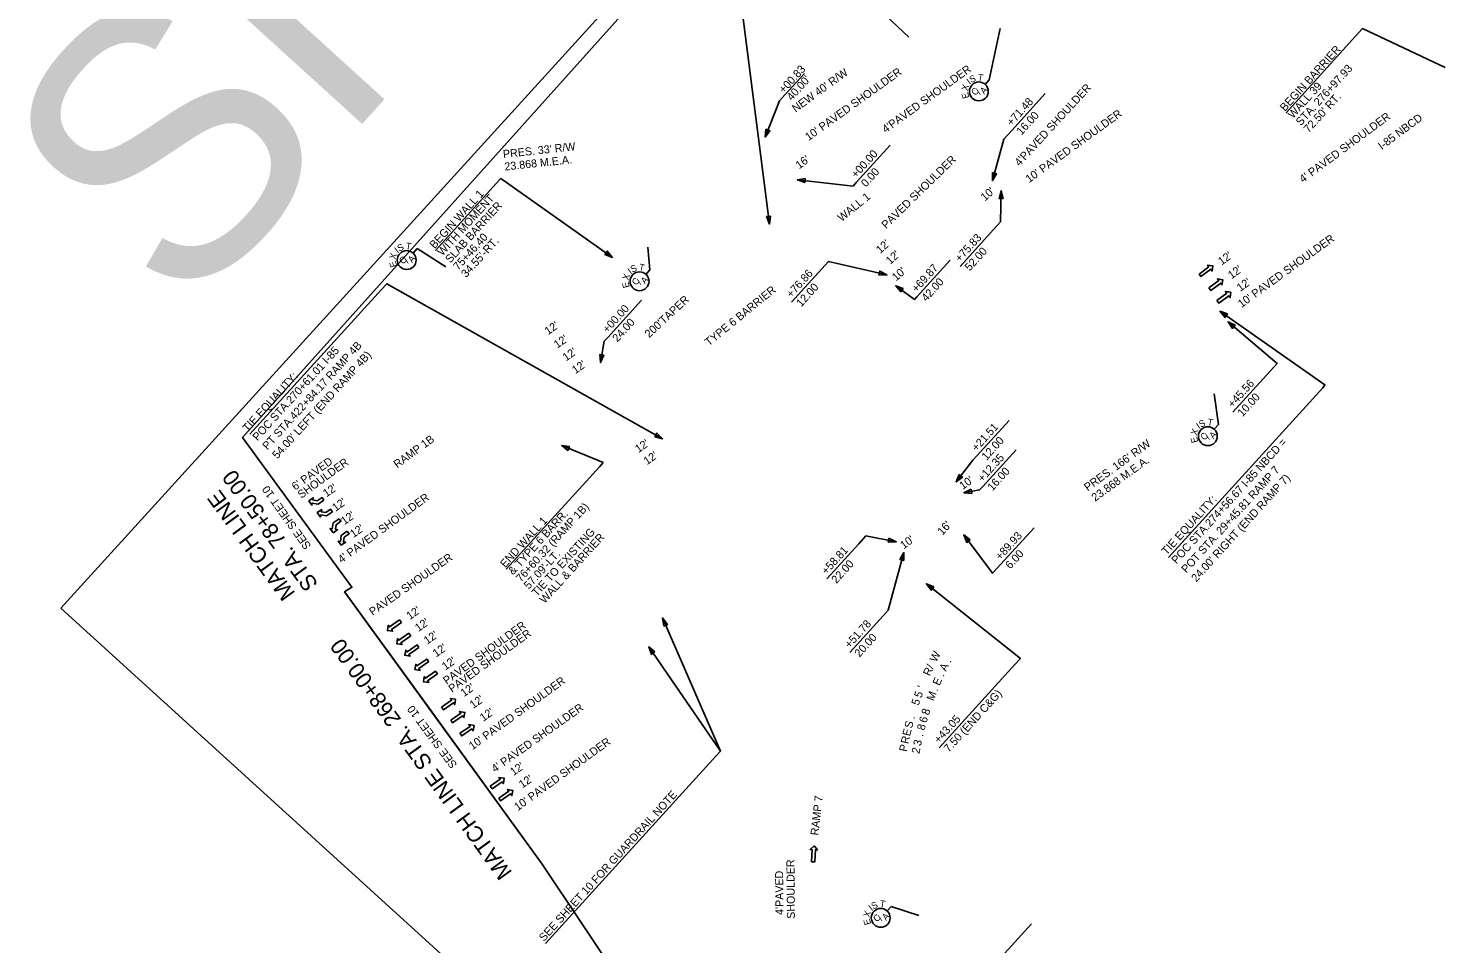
# Model space of a CAD drawing. Extents: x 1608705 to 1610581, y 1091647 to 1093887.
# Drawn here: x 1608705 to 1609761, y 1092394 to 1093080 of the extents above; entities that cross this region are included whole.
import ezdxf

# ---------------------------------------------------------------- set-up
doc = ezdxf.new("R2010")
doc.units = 0
for name, color, linetype in [('Level 14', 7, 'Continuous'), ('Level 2', 7, 'Continuous'), ('Plan_Clip', 7, 'Continuous'), ('RD_EX_Control_Access', 7, 'Continuous'), ('RD_EX_RW_TX', 7, 'Continuous'), ('RD_PD_GR_TX', 7, 'Continuous'), ('RD_PD_RW_TX', 7, 'Continuous'), ('RD_SHT_MatchLine', 7, 'Continuous'), ('RD_SHT_Misc1', 7, 'Continuous'), ('RD_SHT_TX', 7, 'Continuous'), ('RD_TX_RoadID', 7, 'Continuous'), ('RD_TX_RW', 7, 'Continuous')]:
    doc.layers.add(name, color=color, linetype=linetype)

msp = doc.modelspace()

# ---------------------------------------------------------------- linework, layer by layer
at = {"layer": 'Level 14'}
for points in [[(1609582.6, 1092896), (1609584, 1092894.1), (1609591.4, 1092899.6), (1609592.3, 1092898.3), (1609592.9, 1092902.2), (1609589, 1092902.8), (1609589.9, 1092901.5)], [(1609590, 1092885.6), (1609591.4, 1092883.7), (1609598.8, 1092889.2), (1609599.7, 1092887.9), (1609600.3, 1092891.8), (1609596.4, 1092892.4), (1609597.3, 1092891.1)], [(1609596, 1092876.2), (1609597.4, 1092874.3), (1609604.8, 1092879.7), (1609605.8, 1092878.4), (1609606.4, 1092882.4), (1609602.4, 1092883), (1609603.4, 1092881.7)], [(1608926.5, 1092726.4), (1608922.1, 1092723.4), (1608917.7, 1092724.2), (1608917.4, 1092722.6), (1608915.1, 1092725.9), (1608918.4, 1092728.2), (1608918.1, 1092726.6), (1608921.5, 1092725.9), (1608925.1, 1092728.4)], [(1608932.9, 1092717.6), (1608928.5, 1092714.6), (1608924.1, 1092715.4), (1608923.8, 1092713.8), (1608921.5, 1092717.1), (1608924.8, 1092719.4), (1608924.5, 1092717.8), (1608927.9, 1092717.1), (1608931.5, 1092719.6)], [(1608937.8, 1092712.5), (1608939.2, 1092710.6), (1608935.6, 1092708), (1608935.1, 1092704.6), (1608936.7, 1092704.3), (1608933.4, 1092702), (1608931.1, 1092705.3), (1608932.7, 1092705), (1608933.5, 1092709.4)], [(1608943.9, 1092703.1), (1608945.3, 1092701.1), (1608941.7, 1092698.6), (1608941.1, 1092695.1), (1608942.7, 1092694.9), (1608939.5, 1092692.6), (1608937.2, 1092695.8), (1608938.8, 1092695.5), (1608939.5, 1092700)], [(1608984.5, 1092634.7), (1608983.1, 1092636.6), (1608975.6, 1092631.4), (1608974.7, 1092632.7), (1608974, 1092628.7), (1608977.9, 1092628.1), (1608977, 1092629.4)], [(1608991.5, 1092624.7), (1608990.1, 1092626.7), (1608982.6, 1092621.4), (1608981.7, 1092622.7), (1608981, 1092618.8), (1608985, 1092618.1), (1608984, 1092619.4)], [(1608997.7, 1092616), (1608996.3, 1092618), (1608988.8, 1092612.7), (1608987.8, 1092614), (1608987.1, 1092610.1), (1608991.1, 1092609.4), (1608990.1, 1092610.7)], [(1609005.1, 1092605.4), (1609003.7, 1092607.3), (1608996.2, 1092602.1), (1608995.3, 1092603.4), (1608994.6, 1092599.5), (1608998.5, 1092598.8), (1608997.6, 1092600.1)], [(1609011.5, 1092596.2), (1609010.2, 1092598.1), (1609002.6, 1092592.9), (1609001.7, 1092594.2), (1609001, 1092590.3), (1609005, 1092589.6), (1609004, 1092590.9)], [(1609014.7, 1092571.2), (1609016.1, 1092569.2), (1609023.6, 1092574.5), (1609024.5, 1092573.1), (1609025.2, 1092577.1), (1609021.3, 1092577.8), (1609022.2, 1092576.4)], [(1609021.5, 1092561.4), (1609022.9, 1092559.4), (1609030.4, 1092564.7), (1609031.4, 1092563.4), (1609032.1, 1092567.3), (1609028.1, 1092568), (1609029, 1092566.7)], [(1609028.4, 1092551.6), (1609029.8, 1092549.6), (1609037.3, 1092554.9), (1609038.3, 1092553.5), (1609039, 1092557.5), (1609035, 1092558.2), (1609036, 1092556.8)], [(1609051.2, 1092511.9), (1609052.6, 1092510), (1609060.1, 1092515.2), (1609061, 1092513.9), (1609061.7, 1092517.9), (1609057.7, 1092518.5), (1609058.7, 1092517.2)], [(1609057.5, 1092502.9), (1609058.9, 1092500.9), (1609066.4, 1092506.2), (1609067.4, 1092504.9), (1609068, 1092508.8), (1609064.1, 1092509.5), (1609065, 1092508.2)], [(1609292.1, 1092455.2), (1609294.5, 1092455.1), (1609294.9, 1092464.3), (1609296.5, 1092464.2), (1609293.9, 1092467.2), (1609290.9, 1092464.5), (1609292.5, 1092464.4)]]:
    msp.add_lwpolyline(points, close=True, dxfattribs=at)
at = {"layer": 'Level 2'}
msp.add_lwpolyline([(1608729.1, 1092645.4), (1609856.1, 1093884.6), (1610563.7, 1093241), (1609436.7, 1092001.8)], close=True, dxfattribs=at)
at = {"layer": 'Plan_Clip'}
msp.add_lwpolyline([(1609149.6, 1092364.4), (1609090, 1092453.4), (1608942, 1092657.6), (1608947.4, 1092661.1), (1608865.5, 1092773.4), (1609629.1, 1093625.1), (1609624.6, 1093628.8), (1609641.7, 1093647.8), (1609756.7, 1093668.3), (1609768.8, 1093644), (1609859.4, 1093621.4), (1610115.1, 1093602.3), (1610196.6, 1093489.1), (1610193.3, 1093486.6), (1610273.8, 1093378.2), (1610243.5, 1093357.4), (1610329.6, 1093201), (1610402.7, 1093068.4), (1609510.9, 1092089.3)], dxfattribs=at)
msp.add_lwpolyline([(1609149.6, 1092364.4), (1609090, 1092453.4), (1608942, 1092657.6), (1608947.4, 1092661.1), (1608865.5, 1092773.4), (1609629.1, 1093625.1), (1609624.6, 1093628.8), (1609641.7, 1093647.8), (1609756.7, 1093668.3), (1609768.8, 1093644), (1609859.4, 1093621.4), (1610115.1, 1093602.3), (1610196.6, 1093489.1), (1610193.3, 1093486.6), (1610273.8, 1093378.2), (1610243.5, 1093357.4), (1610329.6, 1093201), (1610402.7, 1093068.4), (1609510.9, 1092089.3)], dxfattribs=at)
at = {"layer": 'RD_EX_Control_Access'}
for p, q in [((1609339.7, 1093097.3), (1609365.1, 1093073.6)), ((1609425.3, 1093041.6), (1609433.5, 1093080.2)), ((1609422.2, 1093038.2), (1609425.3, 1093041.6)), ((1608993.3, 1092911.7), (1608996.4, 1092915.1)), ((1608996.4, 1092915.1), (1609017.8, 1092901.5)), ((1609170.9, 1092899.2), (1609169.3, 1092916.3)), ((1609167.8, 1092895.8), (1609170.9, 1092899.2)), ((1609597.1, 1092783.1), (1609593.9, 1092806.1)), ((1609594, 1092779.7), (1609597.1, 1092783.1)), ((1609348.7, 1092418.5), (1609351.8, 1092421.8)), ((1609351.8, 1092421.8), (1609372.5, 1092415))]:
    msp.add_line(p, q, dxfattribs=at)
for centre in [(1609417.5, 1093033), (1608988.5, 1092906.5), (1609163.1, 1092890.6), (1609589.2, 1092774.4), (1609343.9, 1092413.2)]:
    msp.add_circle(centre, 7.08, dxfattribs=at)
at = {"layer": 'RD_PD_GR_TX'}
for p, q in [((1609223.8, 1092538.3), (1609180.2, 1092638.1)), ((1609215.2, 1092528.9), (1609092.6, 1092394))]:
    msp.add_line(p, q, dxfattribs=at)
for points in [[(1609240.6, 1093094.1), (1609240, 1093093.4), (1609260.4, 1092933.5)], [(1609215.2, 1092528.9), (1609223.8, 1092538.3), (1609170.1, 1092616.5)]]:
    msp.add_lwpolyline(points, dxfattribs=at)
for points in [[(1609258.2, 1092939.1), (1609260.4, 1092933.5), (1609261.2, 1092939.5)], [(1609181.2, 1092632), (1609180.2, 1092638.1), (1609184, 1092633.2)], [(1609174.6, 1092612.6), (1609170.1, 1092616.5), (1609172.1, 1092610.8)]]:
    msp.add_lwpolyline(points, close=True, dxfattribs=at)
at = {"layer": 'RD_SHT_MatchLine'}
msp.add_line((1608947.4, 1092661.1), (1608865.5, 1092773.4), dxfattribs=at)
msp.add_lwpolyline([(1609090, 1092453.4), (1609002, 1092574.9), (1608942.2, 1092657.4)], dxfattribs=at)
at = {"layer": 'RD_SHT_TX'}
for p, q in [((1609702.2, 1093076.8), (1609647.8, 1093016.9)), ((1609467.3, 1093031.3), (1609442.2, 1093003.7)), ((1609351, 1092992.6), (1609325.6, 1092964.7)), ((1609058.2, 1092966.8), (1609010.1, 1092913.8)), ((1609428.5, 1092929.4), (1609403.4, 1092901.8)), ((1609302.3, 1092902.7), (1609277, 1092874.9)), ((1609396, 1092906.5), (1609371, 1092878.9)), ((1609392.9, 1092895.1), (1609392.9, 1092895.1)), ((1608969.5, 1092884.4), (1608870.8, 1092775.9)), ((1609164.6, 1092876.4), (1609139.2, 1092848.5)), ((1609633.2, 1092820.3), (1609607.9, 1092792.5)), ((1609675.3, 1092810.6), (1609559.7, 1092683.5)), ((1609440.1, 1092786.2), (1609416, 1092759.8)), ((1609445.5, 1092764.3), (1609420.4, 1092736.8)), ((1609133.2, 1092751.8), (1609063.1, 1092674.7)), ((1609458.9, 1092705.8), (1609433.8, 1092678.3)), ((1609327.5, 1092693.8), (1609303.4, 1092667.4)), ((1609345.8, 1092639.8), (1609320.8, 1092612.2)), ((1609444.5, 1092603.2), (1609387.7, 1092540.8)), ((1609456.9, 1092408.8), (1609352.1, 1092293.6))]:
    msp.add_line(p, q, dxfattribs=at)
for points in [[(1609702.2, 1093076.8), (1609705.2, 1093080.1), (1609767, 1093050.8)], [(1609442.2, 1093003.7), (1609436.3, 1092997.2), (1609427.7, 1092966.1)], [(1609058.2, 1092966.8), (1609059.1, 1092967.7), (1609142.7, 1092908.5)], [(1609325.6, 1092964.7), (1609323.2, 1092962), (1609281.4, 1092966.8)], [(1609428.5, 1092929.4), (1609433.7, 1092935.1), (1609434.2, 1092958.6)], [(1609302.3, 1092902.7), (1609304.8, 1092905.5), (1609348.5, 1092895.4)], [(1608969.5, 1092884.4), (1608973.5, 1092888.7), (1609180.4, 1092772.5)], [(1609371, 1092878.9), (1609369.2, 1092877), (1609355.2, 1092887.3)], [(1609675.3, 1092810.6), (1609677, 1092813), (1609598.2, 1092868.1)], [(1609633.2, 1092820.3), (1609641.1, 1092829), (1609604.3, 1092860.2)], [(1609139.2, 1092848.5), (1609136.6, 1092845.7), (1609133.9, 1092829.6)], [(1609133.2, 1092751.8), (1609135.8, 1092754.6), (1609104.7, 1092767.4)], [(1609416, 1092759.8), (1609412.9, 1092756.4), (1609400.5, 1092740.1)], [(1609420.4, 1092736.8), (1609418, 1092734.1), (1609406.3, 1092732)], [(1609327.5, 1092693.8), (1609332.8, 1092699.6), (1609355.5, 1092695.3)], [(1609433.8, 1092678.3), (1609427.8, 1092671.6), (1609406.1, 1092700.4)], [(1609345.8, 1092639.8), (1609349.6, 1092643.9), (1609361.3, 1092687.2)], [(1609444.5, 1092603.2), (1609448.6, 1092607.7), (1609378.2, 1092663.8)]]:
    msp.add_lwpolyline(points, dxfattribs=at)
for points in [[(1609427.7, 1092972.1), (1609427.7, 1092966.1), (1609430.7, 1092971.3)], [(1609287.3, 1092967.7), (1609281.4, 1092966.8), (1609287, 1092964.6)], [(1609435.7, 1092952.8), (1609434.2, 1092958.6), (1609432.6, 1092952.8)], [(1609137.1, 1092910.6), (1609142.7, 1092908.5), (1609138.9, 1092913.2)], [(1609342.5, 1092895.2), (1609348.5, 1092895.4), (1609343.2, 1092898.2)], [(1609360.8, 1092885.2), (1609355.2, 1092887.3), (1609358.9, 1092882.7)], [(1609603.9, 1092866.1), (1609598.2, 1092868.1), (1609602.1, 1092863.5)], [(1609609.7, 1092857.6), (1609604.3, 1092860.2), (1609607.7, 1092855.2)], [(1609133.3, 1092835.6), (1609133.9, 1092829.6), (1609136.4, 1092835.1)], [(1609174.6, 1092774), (1609180.4, 1092772.5), (1609176.1, 1092776.7)], [(1609110.6, 1092766.6), (1609104.7, 1092767.4), (1609109.4, 1092763.7)], [(1609402.8, 1092745.7), (1609400.5, 1092740.1), (1609405.2, 1092743.8)], [(1609411.8, 1092734.6), (1609406.3, 1092732), (1609412.3, 1092731.5)], [(1609349.5, 1092694.9), (1609355.5, 1092695.3), (1609350.1, 1092697.9)], [(1609410.9, 1092696.7), (1609406.1, 1092700.4), (1609408.4, 1092694.8)], [(1609361.3, 1092681.2), (1609361.3, 1092687.2), (1609358.3, 1092682)], [(1609383.7, 1092661.4), (1609378.2, 1092663.8), (1609381.8, 1092658.9)]]:
    msp.add_lwpolyline(points, close=True, dxfattribs=at)
at = {"layer": 'RD_TX_RW'}
msp.add_line((1609286.7, 1093046.5), (1609272, 1093030.3), dxfattribs=at)
msp.add_lwpolyline([(1609272, 1093030.3), (1609267.9, 1093025.8), (1609257.2, 1092998.7)], dxfattribs=at)
msp.add_lwpolyline([(1609257.8, 1093004.6), (1609257.2, 1092998.7), (1609260.7, 1093003.5)], close=True, dxfattribs=at)

# ---------------------------------------------------------------- texts
at = {"layer": 'RD_EX_Control_Access'}
for s, rotation, p in [('T', 350.7639, (1609416.4, 1093041.3)), ('X', 72.8073, (1609409, 1093033.1)), ('I', 37.6458, (1609410.6, 1093037.9)), ('S', 25.9253, (1609411.8, 1093039.2)), ('C', 47.7105, (1609414.8, 1093029.5)), ('/', 47.7105, (1609418.4, 1093030.3)), ('A', 47.7105, (1609421.5, 1093030.5)), ('E', 106.2944, (1609410.4, 1093028.4)), ('T', 350.7639, (1608987.5, 1092914.8)), ('X', 72.8073, (1608980.1, 1092906.6)), ('I', 37.6458, (1608981.7, 1092911.4)), ('S', 25.9253, (1608982.9, 1092912.7)), ('C', 47.7105, (1608985.9, 1092903)), ('/', 47.7105, (1608989.5, 1092903.8)), ('A', 47.7105, (1608992.6, 1092904)), ('E', 106.2944, (1608981.4, 1092901.9)), ('I', 35.6937, (1609156.4, 1092895.7)), ('S', 23.9732, (1609157.6, 1092897)), ('T', 348.8117, (1609162.3, 1092898.9)), ('X', 70.8551, (1609154.7, 1092891)), ('E', 104.3423, (1609155.8, 1092886.3)), ('C', 47.7105, (1609160.4, 1092887.1)), ('/', 47.7105, (1609164, 1092887.8)), ('A', 47.7105, (1609167.1, 1092888.1)), ('I', 35.6937, (1609582.6, 1092779.6)), ('S', 23.9732, (1609583.8, 1092780.8)), ('T', 348.8117, (1609588.5, 1092782.8)), ('E', 104.3423, (1609582, 1092770.1)), ('X', 70.8551, (1609580.8, 1092774.8)), ('C', 47.7105, (1609586.6, 1092770.9)), ('/', 47.7105, (1609590.1, 1092771.7)), ('A', 47.7105, (1609593.3, 1092772)), ('I', 37.6458, (1609337.1, 1092418.2)), ('S', 25.9253, (1609338.3, 1092419.4)), ('T', 350.7639, (1609342.9, 1092421.6)), ('X', 72.8073, (1609335.5, 1092413.3)), ('E', 106.2944, (1609336.8, 1092408.7)), ('C', 47.7105, (1609341.3, 1092409.7)), ('/', 47.7105, (1609344.8, 1092410.5)), ('A', 47.7105, (1609348, 1092410.8))]:
    msp.add_text(s, height=5, rotation=rotation, dxfattribs=at).set_placement(p)
at = {"layer": 'RD_EX_RW_TX'}
for s, rotation, p in [("PRES. 33' R/W", 6.1856, (1609061, 1092983)), ('23.868 M.E.A.', 6.1856, (1609062.1, 1092973.6)), ("PRES. 166' R/W", 35.9902, (1609499.1, 1092732.9)), ('23.868 M.E.A.', 35.9902, (1609504.7, 1092725.2)), ('W', 63.0961, (1609385.6, 1092604.5)), ('/', 64.4586, (1609383.2, 1092599.4)), ('A', 63.8456, (1609392.9, 1092597.6)), ('.', 62.4298, (1609396.2, 1092604.2)), ('R', 65.821, (1609380.8, 1092594.1)), ('E', 66.6771, (1609388, 1092586.9)), ('.', 65.2613, (1609391, 1092593.6)), ('5', 69.9084, (1609374.3, 1092577.7)), ("'", 68.5459, (1609376.8, 1092584.4)), ('M', 69.5086, (1609383.6, 1092575.5)), ('.', 68.0928, (1609386.3, 1092582.7)), ('5', 71.2708, (1609372.3, 1092572.1)), ('S', 75.3582, (1609367.3, 1092554.9)), ('.', 73.9957, (1609369.2, 1092561.9)), ('6', 73.7559, (1609378.2, 1092559)), ('8', 72.3401, (1609379.9, 1092564.8)), ('R', 78.0831, (1609364.7, 1092543.3)), ('E', 76.7206, (1609365.9, 1092549.1)), ('8', 75.1716, (1609376.7, 1092553.4)), ('.', 76.5874, (1609375.6, 1092548.8)), ('P', 79.4456, (1609363.5, 1092537.5)), ('2', 79.4189, (1609372.9, 1092536)), ('3', 78.0031, (1609374, 1092541.8))]:
    msp.add_text(s, height=6, rotation=rotation, dxfattribs=at).set_placement(p)
at = {"layer": 'RD_PD_GR_TX'}
msp.add_text('SEE SHEET 10 FOR GUARDRAIL NOTE', height=6, rotation=47.7138, dxfattribs=at).set_placement((1609091.5, 1092395.1))
at = {"layer": 'RD_PD_RW_TX'}
msp.add_text("NEW 40' R/W", height=6, rotation=35.9184, dxfattribs=at).set_placement((1609280.1, 1093017))
at = {"layer": 'RD_SHT_MatchLine'}
for s, height, rotation, p in [('STA. 78+50.00', 12, 126.2181, (1608922.6, 1092663.7)), ('MATCH LINE', 12, 126.2181, (1608905.4, 1092656.7)), ('SEE SHEET 10', 6, 125.5072, (1608917.1, 1092692.2)), ('MATCH LINE STA. 268+00.00', 12, 125.9283, (1609068, 1092447.3)), ('SEE SHEET 10', 6, 126.6022, (1609026.7, 1092528.1))]:
    msp.add_text(s, height=height, rotation=rotation, dxfattribs=at).set_placement(p)
at = {"layer": 'RD_SHT_Misc1'}
msp.add_text('SHEET 11', height=200, rotation=47.7138, dxfattribs=at).set_placement((1608820.3, 1092860.4))
at = {"layer": 'RD_SHT_TX'}
for s, rotation, p in [('BEGIN BARRIER', 47.7138, (1609647, 1093017.6)), ("10' PAVED SHOULDER", 35.7864, (1609289.9, 1092995.7)), ("4'PAVED SHOULDER", 35.9579, (1609347.6, 1093001.5)), ('STA. 276+97.93', 47.7138, (1609658.9, 1093006.8)), ("4'PAVED SHOULDER", 47.374, (1609448, 1092976.5)), ('WALL 39', 47.7138, (1609653, 1093012.2)), ('+71.48', 47.7138, (1609442.1, 1093006.6)), ("72.50' RT.", 47.7138, (1609664.8, 1093001.5)), ('16.00', 47.7138, (1609449.5, 1092999.8)), ("10' PAVED SHOULDER", 35.9181, (1609455.2, 1092964.2)), ("4' PAVED SHOULDER", 36.4527, (1609660.5, 1092964.1)), ("16'", 36.6282, (1609282.8, 1092974.5)), ('+00.00', 47.7138, (1609325.5, 1092967.5)), ('PAVED SHOULDER', 44.3376, (1609348, 1092929.6)), ('0.00', 47.7138, (1609332.9, 1092960.8)), ("10'", 41.1165, (1609422, 1092950.4)), ('BEGIN WALL 1', 47.7138, (1609009.4, 1092914.6)), ('WITH MOMENT ', 47.7138, (1609015.3, 1092909.2)), ('WALL 1', 39.2165, (1609314.6, 1092935)), ('SLAB BARRIER', 47.7138, (1609021.2, 1092903.8)), ('75+46.40', 47.7138, (1609027.2, 1092898.4)), ("34.55'-RT.", 47.7138, (1609033.1, 1092893)), ("12'", 42.0548, (1609343.6, 1092911)), ('+75.83', 47.7138, (1609403.3, 1092904.6)), ("10' PAVED SHOULDER", 35.9181, (1609614.4, 1092870.5)), ("12'", 42.0548, (1609351, 1092902.8)), ('52.00', 47.7138, (1609410.7, 1092897.9)), ("12'", 35.6442, (1609599.5, 1092902.4)), ('+76.86', 47.7138, (1609276.9, 1092877.8)), ("10'", 41.1165, (1609355.5, 1092890.4)), ('+69.87', 47.7138, (1609370.8, 1092881.8)), ("12'", 35.6442, (1609606.9, 1092892)), ('12.00', 47.7138, (1609284.3, 1092871)), ('42.00', 47.7138, (1609378.2, 1092875)), ("12'", 35.6442, (1609613.5, 1092882.6)), ("200'TAPER", 42.93, (1609170.3, 1092847.8)), ('TYPE 6 BARRIER', 39.2165, (1609215.1, 1092841.7)), ('+00.00', 47.7138, (1609139.1, 1092851.4)), ("12'", 35.0535, (1609094.5, 1092850.1)), ('24.00', 47.7138, (1609146.5, 1092844.6)), ('PT STA.422+84.17 RAMP 4B', 47.7121, (1608884.1, 1092763.8)), ("12'", 35.0535, (1609101.4, 1092840)), ('POC STA.270+61.01 I-85', 47.7121, (1608876.7, 1092770.5)), ("54.00' LEFT (END RAMP 4B)", 47.7121, (1608891.5, 1092757)), ("12'", 35.0535, (1609108, 1092830.4)), ("12'", 35.0535, (1609115, 1092820.9)), ('TIE EQUALITY:', 47.7121, (1608869.3, 1092777.2)), ('+45.56', 47.7138, (1609607.8, 1092795.3)), ('10.00', 47.7138, (1609615.2, 1092788.6)), ('+21.51', 47.7138, (1609415.9, 1092762.6)), ("12'", 35.0535, (1609162.3, 1092761.7)), ('12.00', 47.7138, (1609423.3, 1092755.9)), ('POC STA.274+56.67 I-85 NBCD =', 47.7121, (1609565.7, 1092678.2)), ("12'", 35.0535, (1609168.7, 1092752.6)), ('+12.35', 47.7138, (1609420.3, 1092739.6)), ("6' PAVED", 36.0871, (1608905, 1092733.5)), ('SHOULDER', 36.0871, (1608909.5, 1092727.4)), ('16.00', 47.7138, (1609427.7, 1092732.9)), ('POT STA. 29+45.81 RAMP 7', 47.7121, (1609573.1, 1092671.4)), ("10'", 35.0468, (1609405.4, 1092734.1)), ("24.00' RIGHT (END RAMP 7)", 47.7121, (1609580.5, 1092664.7)), ("12'", 35.0535, (1608928.3, 1092728.4)), ("4' PAVED SHOULDER", 36.0871, (1608939.6, 1092678.9)), ('TIE EQUALITY:', 47.7121, (1609558.3, 1092684.9)), ("12'", 35.0535, (1608935.2, 1092717.7)), ("12'", 35.0535, (1608941.8, 1092707.7)), ('76+60.32 (RAMP 1B)', 47.7138, (1609074.2, 1092664.6)), ("12'", 35.0535, (1608948.6, 1092698)), ('END WALL 1', 47.7138, (1609062.4, 1092675.4)), ('& TYPE 6 BARR.', 47.7138, (1609068.3, 1092670)), ("16'", 47.7138, (1609390.2, 1092699.7)), ('TIE TO EXISTING ', 47.7138, (1609086.1, 1092653.8)), ('WALL & BARRIER', 47.7138, (1609092, 1092648.5)), ("10'", 35.6925, (1609361.1, 1092689.5)), ('+89.93', 47.7138, (1609433.7, 1092681.1)), ("57.09'-LT.", 47.7138, (1609080.1, 1092659.2)), ('+58.81', 47.7138, (1609303.3, 1092670.2)), ('6.00', 47.7138, (1609441.1, 1092674.4)), ('PAVED SHOULDER', 35.1629, (1608963, 1092639.6)), ('22.00', 47.7138, (1609310.7, 1092663.5)), ("12'", 35.0535, (1608990.9, 1092636.5)), ("12'", 35.0535, (1608997.3, 1092627.5)), ('PAVED SHOULDER', 35.8553, (1609018.5, 1092587.9)), ('+51.78', 47.7138, (1609320.6, 1092615)), ("12'", 35.0535, (1609003.9, 1092618)), ('PAVED SHOULDER', 35.8553, (1609022.5, 1092581.9)), ('20.00', 47.7138, (1609328, 1092608.3)), ("12'", 35.0535, (1609010.6, 1092608.4)), ("12'", 35.0535, (1609017.5, 1092598.6)), ("10' PAVED SHOULDER", 35.9181, (1609037.8, 1092538.9)), ("12'", 35.0535, (1609031.5, 1092578.7)), ('7.50 (END C&G)', 47.7138, (1609395, 1092536.9)), ("12'", 35.0468, (1609038.4, 1092569.8)), ("12'", 35.0468, (1609045.9, 1092560.2)), ("4' PAVED SHOULDER", 35.4763, (1609054.7, 1092521.9)), ('+43.05', 47.7138, (1609387.6, 1092543.6)), ("10' PAVED SHOULDER", 35.9181, (1609071.8, 1092493.2)), ("12'", 35.0468, (1609068.6, 1092519.5)), ("12'", 35.0468, (1609075.2, 1092510.1)), ('SHOULDER', 90.5113, (1609279.6, 1092412.5)), ("4'PAVED", 90.5113, (1609271, 1092415.4))]:
    msp.add_text(s, height=6, rotation=rotation, dxfattribs=at).set_placement(p)
at = {"layer": 'RD_TX_RoadID'}
for s, rotation, p in [('I-85 NBCD', 36.62, (1609719.6, 1092988.8)), ('RAMP 1B', 36.0871, (1608981.4, 1092750.2)), ('RAMP 7', 83.4435, (1609297.1, 1092474.8))]:
    msp.add_text(s, height=6, rotation=rotation, dxfattribs=at).set_placement(p)
at = {"layer": 'RD_TX_RW'}
for s, p in [('+00.83', (1609271.3, 1093031)), ("40.00'", (1609277.2, 1093025.6))]:
    msp.add_text(s, height=6, rotation=47.7138, dxfattribs=at).set_placement(p)

doc.saveas('drawing.dxf')
